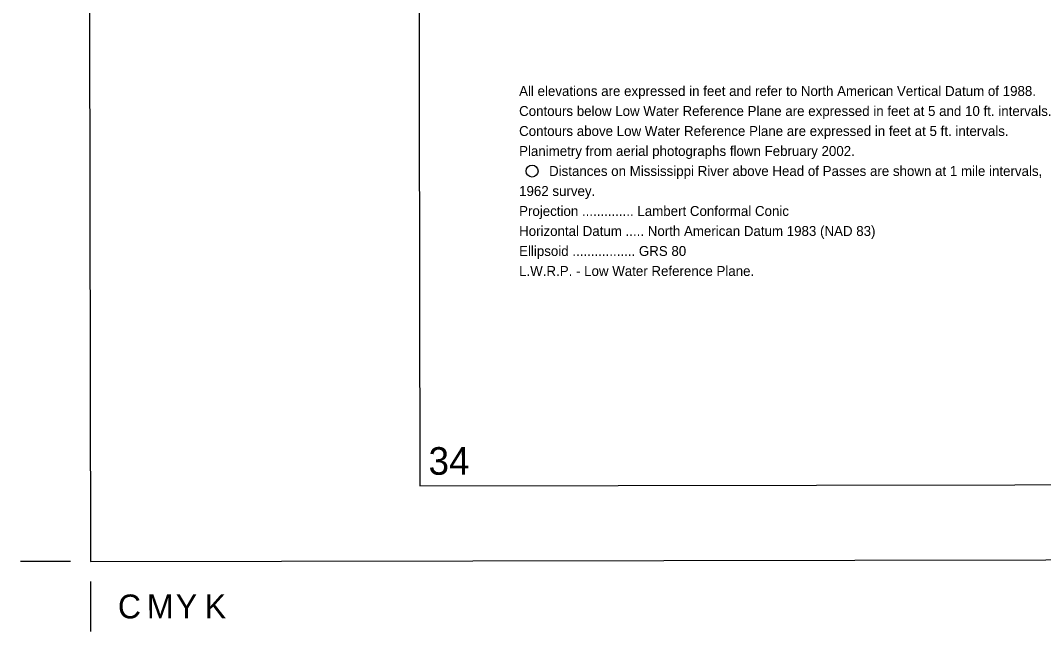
# Model space of a CAD drawing. Extents: x 3324125 to 3362000, y 600753 to 626151.
# Drawn here: x 3324167 to 3332702, y 600753 to 605847 of the extents above; entities that cross this region are included whole.
import ezdxf

# ---------------------------------------------------------------- set-up
doc = ezdxf.new("R2010")
doc.units = 0
for name, color, linetype in [('G-ANNO-NPLT', 7, 'Continuous'), ('V-ANNO-DIMS', 7, 'Continuous'), ('V-ANNO-NOTE', 7, 'Continuous'), ('V-ANNO-SYMB', 7, 'Continuous'), ('V-ANNO-TEXT', 7, 'Continuous')]:
    doc.layers.add(name, color=color, linetype=linetype)

msp = doc.modelspace()

# ---------------------------------------------------------------- linework, layer by layer
at = {"layer": 'G-ANNO-NPLT'}
msp.add_lwpolyline([(3324750.5, 601336.7), (3361417.2, 601400.7), (3361375, 625567.3), (3324708.4, 625503.3)], close=True, dxfattribs=at)
at = {"layer": 'V-ANNO-DIMS'}
for p, q in [((3324583.9, 601336.4), (3324167.2, 601335.7)), ((3324750.8, 601170), (3324751.6, 600753.4))]:
    msp.add_line(p, q, dxfattribs=at)
at = {"layer": 'V-ANNO-NOTE'}
msp.add_circle((3328435.4, 604592.1), 50, dxfattribs=at)
at = {"layer": 'V-ANNO-SYMB'}
msp.add_lwpolyline([(3327499.6, 601966.6), (3360582.7, 602024.3), (3360542.7, 624940.8), (3327459.6, 624883.1), (3327499.6, 601966.6)], dxfattribs=at)

# ---------------------------------------------------------------- texts
at = {"layer": 'V-ANNO-DIMS'}
for s, p in [('C', (3324980.3, 600862.5)), ('M', (3325222, 600862.9)), ('Y', (3325463.7, 600863.3)), ('K', (3325705.3, 600863.7))]:
    msp.add_text(s, height=199.3, rotation=0.1, dxfattribs=at).set_placement(p)
at = {"layer": 'V-ANNO-NOTE'}
for s, rotation, p in [('All elevations are expressed in feet and refer to North American Vertical Datum of 1988.', 0.00001, (3328327.2, 605217.4)), ('Contours below Low Water Reference Plane are expressed in feet at 5 and 10 ft. intervals.', 0.00001, (3328327.2, 605050.7)), ('Contours above Low Water Reference Plane are expressed in feet at 5 ft. intervals.', 0.00001, (3328327.2, 604884)), ('Planimetry from aerial photographs flown February 2002.', 0.00001, (3328327.2, 604717.3)), ('Distances on Mississippi River above Head of Passes are shown at 1 mile intervals,', 0.00001, (3328577.4, 604550.6)), ('1962 survey.', 0.00001, (3328327.2, 604383.9)), ('Projection .............. Lambert Conformal Conic', 359.99998, (3328327.2, 604217.2)), ('Horizontal Datum ..... North American Datum 1983 (NAD 83)', 359.99998, (3328327.2, 604050.5)), ('Ellipsoid ................. GRS 80', 359.99998, (3328327.2, 603883.8)), ('L.W.R.P. - Low Water Reference Plane.', 359.99998, (3328327.2, 603717.1))]:
    msp.add_text(s, height=83, rotation=rotation, dxfattribs=at).set_placement(p)
at = {"layer": 'V-ANNO-TEXT'}
msp.add_text('34', height=230, rotation=0.1, dxfattribs=at).set_placement((3327571.9, 602060))

doc.saveas('drawing.dxf')
